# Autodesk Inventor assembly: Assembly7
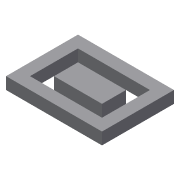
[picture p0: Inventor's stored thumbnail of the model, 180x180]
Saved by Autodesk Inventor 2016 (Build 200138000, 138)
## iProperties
Created: 2015-05
Part Number: Assembly7
Document SubType Name: Assembly
Designer: Sandeep
Author: Sandeep
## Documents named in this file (3)
- C:\Autodesk Inventor 2016\C14\tut_02\Assembly7.iam
- C:\Users\Public\Documents\Autodesk\Inventor 2016\Part10.ipt
- C:\Users\Public\Documents\Autodesk\Inventor 2016\inner plate.ipt
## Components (2 placed, 2 different names)
1. Part10:1 — Flush:1, Flush:2, Flush:3, Mate:1, Mate:2, Mate:3, Mate:4
2. inner plate:1 — Flush:1, Flush:2, Flush:3, Mate:1, Mate:2, Mate:3, Mate:4
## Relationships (7: Mate 4, Flush 3)
- Flush:1: Part10:1 ↔ inner plate:1
- Flush:2: Part10:1 ↔ inner plate:1
- Flush:3: Part10:1 ↔ inner plate:1
- Mate:1: Part10:1 ↔ inner plate:1
- Mate:2: Part10:1 ↔ inner plate:1
- Mate:3: Part10:1 ↔ inner plate:1
- Mate:4: Part10:1 ↔ inner plate:1
